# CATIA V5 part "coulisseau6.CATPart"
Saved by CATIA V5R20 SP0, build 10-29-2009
Part number: coulisseau6
Bounding box of the stored display mesh (mm): x 0 to 10, y -6.86 to 7.893, z -13.154 to 13.037
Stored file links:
  C:\Users\thinkmotion1\Desktop\IAO OK\IAO_2010_1458_splanchena\Correction_Khaled\coulisseau6.CATPart
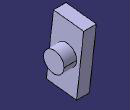
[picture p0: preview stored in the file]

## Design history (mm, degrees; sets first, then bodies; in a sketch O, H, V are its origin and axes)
Body1 (main body)
  Sketch1 on yz-plane, origin (0, 0, 0), H (0, 1, 0), V (0, 0, 1)
    line L1 (-6.8598, -11.8046) -> (-4.0537, 13.0374)
    line L2 (-4.0537, 13.0374) -> (7.8927, 11.6879)
    line L3 (7.8927, 11.6879) -> (5.0866, -13.1541)
    line L4 (5.0866, -13.1541) -> (-6.8598, -11.8046)
    length L1 = 25
    perpendicularity: L2 L1
    parallelism: L3 L1, L4 L2
  Pad1: profile Sketch1, direction (1, 0, 0), length 5
  Sketch2 on end face of Pad1, origin (5, 0, 0), H (0, 1, 0), V (0, 0, 1)
    circle A1 centre (1.1092, 0.4012) radius 4
    radius A1 = 4
  Pad2: profile Sketch2, direction (1, 0, 0), length 5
